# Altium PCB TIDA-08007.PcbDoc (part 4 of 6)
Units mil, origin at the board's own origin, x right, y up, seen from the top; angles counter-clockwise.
Board outline 4212.6 x 2047.24 mil, 10 copper layers (Top Layer, GND 1, Signal Layer 1, GND 2, Split PWR 1, Split PWR 2, GND 3, Signal Layer 2, GND 4, Bottom Layer), stack 66.4 mil thick; 291 components, 178 nets, 1281 pads, 873 vias.
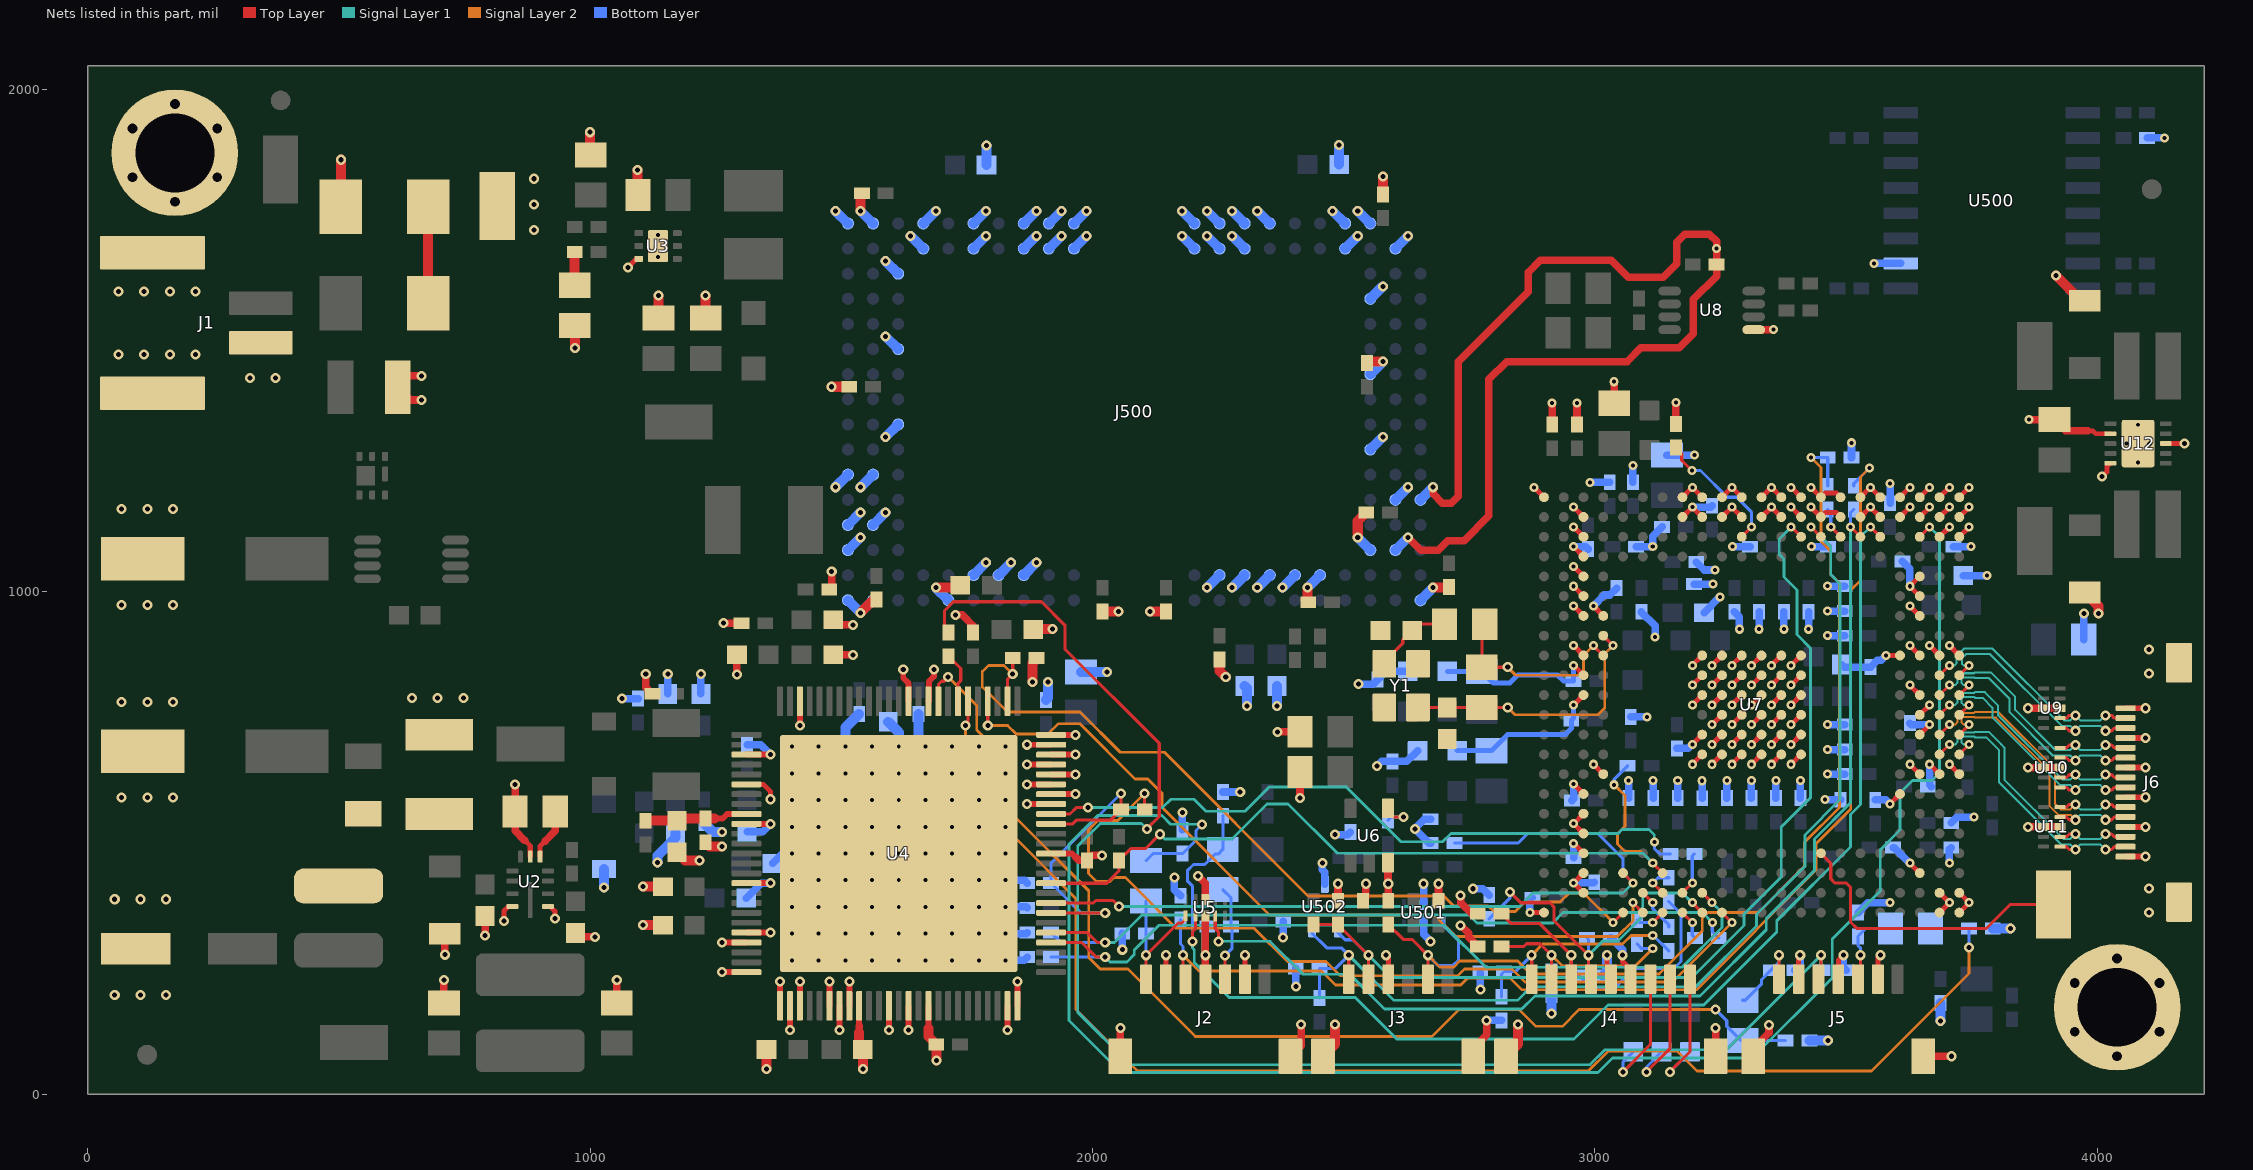
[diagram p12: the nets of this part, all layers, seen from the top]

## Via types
v1: diameter 20, hole 10, Top Layer to Bottom Layer, tented both sides, 439 vias
v2: diameter 18, hole 8, Top Layer to Bottom Layer, tented both sides, 335 vias
v3: diameter 19.68, hole 7.87, Top Layer to Bottom Layer, tented both sides, 72 vias
v4: diameter 19.68, hole 7.87, Top Layer to Bottom Layer, tented bottom, 15 vias
v5: diameter 39.37, hole 19.68, Top Layer to Bottom Layer, 12 vias

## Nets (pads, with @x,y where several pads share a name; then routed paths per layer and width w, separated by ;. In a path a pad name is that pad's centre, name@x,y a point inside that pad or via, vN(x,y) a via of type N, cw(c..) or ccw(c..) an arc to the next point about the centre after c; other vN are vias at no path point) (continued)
GND: C1.2 C2.2 C3.2 C4.2 C6.2 C7.2 C8.1 C9.2 C10.2 C11.2 C13.2 C14.2 C15.2 C16.2 C17.2 C18.2 C19.2 C20.2 C21.2 C22.2 C23.2 C24.2 C25.2 C26.2 C27.2 C28.2 C29.2 C30.2 C31.2 C32.2 C33.2 C34.2 C35.2 C36.2 C37.2 C38.2 C39.2 C40.2 C41.2 C42.2 C43.2 C44.2 C45.2 C46.2 C47.2 C48.2 C49.2 C50.2 C52.2 C53.2 C54.2 C55.2 C500.2 C501.2 C502.2 C503.2 C504.2 C505.2 C506.2 C507.2 C508.2 C509.2 C510.2 C511.2 C512.2 C513.2 C514.2 C515.2 C516.2 C517.2 C518.2 C519.2 C520.2 C521.2 C522.2 C523.2 C524.2 C525.2 C526.2 C527.2 C528.2 C529.2 C530.2 C531.2 C532.2 C533.2 C534.2 C535.2 C536.2 C537.2 C538.2 C539.2 C540.2 C541.2 C542.2 C543.2 C544.2 C545.2 C546.2 C547.2 C548.2 C549.2 C550.2 C551.2 C553.2 C554.2 C556.2 C557.2 C558.2 C559.2 C560.2 C561.2 C564.2 C565.2 C566.2 C567.2 C568.2 C569.2 C570.2 C571.2 C572.2 C573.2 C574.2 C575.2 C576.2 C577.2 C578.2 C579.2 C580.2 C581.2 C582.2 C583.2 C584.2 C585.2 C586.2 C587.2 D1.2 D500.2 FB507.1 FB509.1 J1.2 J1.3 J1.4 J2.2 J2.4 J2.6 J2.8 J2.9 J3.3 J3.7 J3.8 J4.5 J4.6 J4.10 J4.11 J5.2 J5.4 J5.6 J5.8 J5.9 J6.1 J6.4 J6.7 J6.10 J6.13 J6.16 J6.17 J6.18 J500.A3 J500.A4 J500.A7 J500.A8 J500.A9 J500.A10 J500.A11 J500.A12 J500.A13 J500.A15 J500.A17 J500.A19 J500.A20 J500.B2 J500.B4 J500.B8 J500.B9 J500.B10 J500.B11 J500.B12 J500.B13 J500.B15 J500.B17 J500.C18 J500.D3 J500.F18 J500.G3 J500.J18 J500.K3 J500.L19 J500.L20 J500.M1 J500.M2 J500.N19 J500.N20 J500.P2 J500.P3 J500.P20 J500.R5 J500.R6 J500.R7 J500.R8 J500.R9 J500.R13 J500.R14 J500.R15 J500.T1 J500.T16 J500.T19 J500.T20 MH1.1 MH2.1 R3.1 R4.1 R5.1 R7.1 R8.1 R11.1 R12.1 R13.1 R20.1 R21.1 R24.1 R503.1 R505.1 R513.1 R521.1 R527.1 R528.1 R529.1 R530.1 R538.1 R539.1 R541.1 R542.1 R543.1 R544.1 R545.1 R547.1 TP3.1 U2.1 U2.6 U2.11 U3.3 U3.7@1135,1688.5 U4.13 U4.18 U4.19 U4.20 U4.21 U4.22 U4.23 U4.24 U4.25 U4.35 U4.37 U4.48 U4.53 U4.56 U4.60 U4.66 U4.71 U4.72 U4.75 U4.76 U4.77 U4.78 U4.81 U4.82 U4.83 U4.84 U4.87 U4.89 U4.91 U4.99 U4.100 U4.101 U5.3@2224.41,355.21 U5.8@2224.41,388.09 U6.3 U7.A1 U7.A22 U7.AA1 U7.AA2 U7.AA8 U7.AA14 U7.AA20 U7.AA21 U7.AA22 U7.AB1 U7.AB2 U7.AB8 U7.AB14 U7.AB20 U7.AB21 U7.AB22 U7.C2 U7.C3 U7.C4 U7.C5 U7.C6 U7.C7 U7.C14 U7.C16 U7.C17 U7.C18 U7.C19 U7.C20 U7.C21 U7.D8 U7.D16 U7.H21 U7.H22 U7.J9 U7.J10 U7.J12 U7.J13 U7.J14 U7.J21 U7.J22 U7.K9 U7.K10 U7.K11 U7.K12 U7.K13 U7.K14 U7.K21 U7.K22 U7.L9 U7.L10 U7.L11 U7.L12 U7.L13 U7.L14 U7.L21 U7.L22 U7.M9 U7.M10 U7.M11 U7.M12 U7.M13 U7.M14 U7.M21 U7.M22 U7.N9 U7.N10 U7.N11 U7.N12 U7.N13 U7.N14 U7.N21 U7.N22 U7.P9 U7.P10 U7.P11 U7.P12 U7.P13 U7.P14 U7.P21 U7.P22 U7.R21 U7.R22 U7.T21 U7.T22 U7.U21 U7.U22 U7.V21 U7.V22 U7.W7 U7.W14 U7.W21 U7.W22 U7.Y3 U7.Y8 U7.Y10 U7.Y11 U7.Y12 U7.Y14 U7.Y16 U7.Y17 U7.Y18 U7.Y21 U7.Y22 U8.5 U9.3@3925.83,768.49 U9.8@3892.95,768.49 U10.3@3925.83,650.38 U10.8@3892.95,650.38 U11.3@3925.83,532.27 U11.8@3892.95,532.27 U12.2 U12.5 U12.8 U12.11 U500.10 U501.3@2658.95,345.27 U501.8@2658.95,378.14 U502.3 Y1.2 Y1.4 | length 17551.6
  Top Layer w9.45: 3980.55,1320.56 3991.12,1320.56 3996.67,1315.01 U12.2@4025.83,1315.01 ; U12.8@4136.06,1295.32 v1(4172.95,1295.32)
  Top Layer w10: v1(828.18,345.16) 828.18,365.05 836.77,373.64 U2.11@845.26,373.64 ; 869.21,506.07 880.7,494.58 U2.6@880.7,473.05 ; U2.1@916.13,373.64 920.47,373.64 929.52,364.59 v1(929.52,349.82) ; v1(1075,1645.69) 1092.23,1662.91 U3.3@1096.61,1662.91 ; U4.56@1311.02,617.11 1344.73,617.11 1359.28,602.55 v1(1359.28,587.36) ; J2.2@2145.67,229.33 v1(2145.67,276.86) ; J2.6@2303.15,229.33 v1(2303.15,276.86) ; v1(2583.58,276.86) 2588.58,271.86 J3.3@2588.58,229.33 ; v2(2870.58,361.7) U7.A1@2898.42,361.7 ; v2(2878.73,1208.16) U7.A22@2898.42,1188.47 ; v2(2957.47,499.49) U7.C4@2977.16,479.81 ; v2(2957.47,617.61) U7.C7@2977.16,597.92 ; v2(2957.47,893.2) U7.C14@2977.16,873.51 ; v2(2957.47,971.94) U7.C16@2977.16,952.25 ; v2(2957.47,1011.31) U7.C17@2977.16,991.62 ; v2(2957.47,1050.68) U7.C18@2977.16,1030.99 ; v2(2957.47,1090.05) U7.C19@2977.16,1070.36 ; v2(2957.47,1129.42) U7.C20@2977.16,1109.73 ; v2(2957.47,1168.79) U7.C21@2977.16,1149.1 ; U7.C2@2977.16,401.07 v2(2957.47,420.75) U7.C3@2977.16,440.44 ; U7.C5@2977.16,519.18 v2(2957.47,538.86) U7.C6@2977.16,558.55 ; v2(2996.84,656.98) U7.D8@3016.53,637.29 ; v2(2996.84,971.94) U7.D16@3016.53,952.25 ; v1(3024.01,276.86) 3024.01,255.75 3031.5,248.26 J4.5@3031.5,229.33 ; v1(3054.89,276.86) 3054.89,264.37 3070.87,248.4 J4.6@3070.87,229.43 ; U7.H21@3174.01,1149.1 v2(3193.69,1168.79) U7.J21@3213.38,1149.1 ; U7.H22@3174.01,1188.47 v2(3193.69,1208.16) U7.J22@3213.38,1188.47 ; v2(3193.69,656.98) U7.J9@3213.38,676.66 ; v2(3193.69,696.35) U7.J10@3213.38,716.03 ; v2(3193.69,775.09) U7.J12@3213.38,794.77 ; v2(3193.69,814.46) U7.J13@3213.38,834.14 ; v2(3193.69,853.83) U7.J14@3213.38,873.51 ; v2(3233.06,656.98) U7.K9@3252.75,676.66 ; v2(3233.06,696.35) U7.K10@3252.75,716.03 ; v2(3233.06,735.72) U7.K11@3252.75,755.4 ; v2(3233.06,775.09) U7.K12@3252.75,794.77 ; v2(3233.06,814.46) U7.K13@3252.75,834.14 ; v2(3233.06,853.83) U7.K14@3252.75,873.51 ; U7.K21@3252.75,1149.1 v2(3272.43,1168.79) U7.L21@3292.12,1149.1 ; U7.K22@3252.75,1188.47 v2(3272.43,1208.16) U7.L22@3292.12,1188.47 ; v2(3272.43,656.98) U7.L9@3292.12,676.66 ; v2(3272.43,696.35) U7.L10@3292.12,716.03 ; v2(3272.43,735.72) U7.L11@3292.12,755.4 ; v2(3272.43,775.09) U7.L12@3292.12,794.77 ; v2(3272.43,814.46) U7.L13@3292.12,834.14 ; v2(3272.43,853.83) U7.L14@3292.12,873.51 ; v2(3311.8,656.98) U7.M9@3331.49,676.66 ; v2(3311.8,696.35) U7.M10@3331.49,716.03 ; v2(3311.8,735.72) U7.M11@3331.49,755.4 ; v2(3311.8,775.09) U7.M12@3331.49,794.77 ; v2(3311.8,814.46) U7.M13@3331.49,834.14 ; v2(3311.8,853.83) U7.M14@3331.49,873.51 ; U7.M21@3331.49,1149.1 v2(3351.17,1168.79) U7.N21@3370.86,1149.1 ; U7.M22@3331.49,1188.47 v2(3351.17,1208.16) U7.N22@3370.86,1188.47 ; v2(3351.17,656.98) U7.N9@3370.86,676.66 ; v2(3351.17,696.35) U7.N10@3370.86,716.03 ; v2(3351.17,735.72) U7.N11@3370.86,755.4 ; v2(3351.17,775.09) U7.N12@3370.86,794.77 ; v2(3351.17,814.46) U7.N13@3370.86,834.14 ; v2(3351.17,853.83) U7.N14@3370.86,873.51 ; v2(3390.54,656.98) U7.P9@3410.23,676.66 ; v2(3390.54,696.35) U7.P10@3410.23,716.03 ; v2(3390.54,735.72) U7.P11@3410.23,755.4 ; v2(3390.54,775.09) U7.P12@3410.23,794.77 ; v2(3390.54,814.46) U7.P13@3410.23,834.14 ; v2(3390.54,853.83) U7.P14@3410.23,873.51 ; v2(3390.54,1168.79) U7.P21@3410.23,1149.1 ; v2(3390.54,1208.16) U7.P22@3410.23,1188.47 ; J5.2@3405.51,229.33 3405.51,273.86 v1(3408.51,276.86) ; v2(3429.91,1168.79) U7.R21@3449.6,1149.1 3458.52,1158.03 3480.04,1158.03 U7.T21@3488.97,1149.1 ; v2(3429.91,1208.16) U7.R22@3449.6,1188.47 3458.3,1197.18 3480.26,1197.18 U7.T22@3488.97,1188.47 ; J5.4@3484.25,229.33 3484.25,266.86 v1(3494.25,276.86) ; U7.U21@3528.34,1149.1 v2(3548.02,1168.79) U7.V21@3567.71,1149.1 ; U7.U22@3528.34,1188.47 v2(3548.02,1208.16) U7.V22@3567.71,1188.47 ; J5.6@3562.99,229.33 3562.99,271.86 v1(3567.99,276.86) ; v2(3579.24,873.51) U7.W14@3607.08,873.51 ; v2(3587.39,578.24) U7.W7@3607.08,597.92 ; U7.W21@3607.08,1149.1 v2(3626.76,1168.79) ; U7.W22@3607.08,1188.47 v2(3626.76,1208.16) ; v2(3626.76,460.12) U7.Y3@3646.45,440.44 ; v2(3626.76,656.98) U7.Y8@3646.45,637.29 ; v2(3626.76,814.46) U7.Y12@3646.45,794.77 ; v2(3626.76,893.2) U7.Y14@3646.45,873.51 ; v2(3626.76,971.94) U7.Y16@3646.45,952.25 ; U7.Y10@3646.45,716.03 v2(3666.13,735.72) ; U7.Y11@3646.45,755.4 v2(3666.13,775.09) ; U7.Y17@3646.45,991.62 v2(3626.76,1011.31) U7.Y18@3646.45,1030.99 ; U7.Y21@3646.45,1149.1 v2(3666.13,1168.79) ; U7.Y22@3646.45,1188.47 v2(3666.13,1208.16) ; v2(3666.13,656.98) U7.AA8@3685.82,637.29 ; v2(3666.13,893.2) U7.AA14@3685.82,873.51 ; U7.AA1@3685.82,361.7 v2(3705.5,381.38) U7.AA2@3685.82,401.07 ; U7.AA20@3685.82,1109.73 v2(3705.5,1129.42) ; U7.AA21@3685.82,1149.1 v2(3705.5,1168.79) ; U7.AA22@3685.82,1188.47 v2(3705.5,1208.16) ; v2(3705.5,656.98) U7.AB8@3725.19,637.29 ; v2(3705.5,893.2) U7.AB14@3725.19,873.51 ; U7.AB1@3725.19,361.7 v2(3744.87,381.38) U7.AB2@3725.19,401.07 ; U7.AB20@3725.19,1109.73 v2(3744.87,1129.42) ; U7.AB21@3725.19,1149.1 v2(3744.87,1168.79) ; U7.AB22@3725.19,1188.47 v2(3744.87,1208.16) ; v1(4009.48,1229.77) 4018.89,1239.18 4018.89,1249.02 U12.5@4025.83,1255.95
  Top Layer w11.81: v1(1262.73,243.09) U4.75@1311.02,243.09 ; v1(1262.73,302.14) U4.72@1311.02,302.14 ; U4.71@1311.02,321.83 v1(1359.32,321.83) ; U4.66@1311.02,420.25 v1(1359.32,420.25) ; U4.60@1311.02,538.36 v1(1359.32,538.36) ; U4.53@1311.02,676.16 v1(1359.32,676.16) ; U4.76@1377.95,176.16 v1(1377.95,224.46) ; v1(1397.64,127.86) U4.77@1397.64,176.16 ; U4.78@1417.32,176.16 v1(1417.32,224.46) ; v1(1417.32,734.16) U4.48@1417.32,782.46 ; U4.81@1476.38,176.16 v1(1476.38,224.46) ; v1(1496.06,127.86) U4.82@1496.06,176.16 ; U4.83@1515.75,176.16 v1(1515.75,224.46) ; 1535.43,136.34 U4.84@1535.43,176.16 ; v1(1594.49,127.86) U4.87@1594.49,176.16 ; v1(1623.11,845.28) 1623.11,828.74 1633.86,817.99 U4.37@1633.86,782.46 ; v1(1633.86,127.86) U4.89@1633.86,176.16 ; 1673.23,131.01 U4.91@1673.23,176.16 ; U4.35@1673.23,782.46 1673.95,783.18 1673.95,821.6 1683.98,831.63 v1(1683.98,845.28) ; v1(1830.71,127.86) U4.99@1830.71,176.16 ; U4.100@1850.39,176.16 v1(1850.39,224.46) ; v1(1869.02,577.74) U4.18@1917.32,577.74 ; v1(1869.02,617.11) U4.20@1917.32,617.11 ; v1(1869.02,656.48) U4.22@1917.32,656.48 ; v1(1869.02,695.85) U4.24@1917.32,695.85 ; U4.13@1917.32,479.31 1958.66,479.31 1966.26,471.71 ; U4.19@1917.32,597.42 v1(1965.62,597.42) ; U4.21@1917.32,636.79 v1(1965.62,636.79) ; U4.23@1917.32,676.16 v1(1965.62,676.16) ; U4.25@1917.32,715.53 v1(1965.62,715.53) ; J6.1@4056.1,473.22 v1(4095.79,473.22) ; J6.4@4056.1,532.27 v1(4095.79,532.27) ; J6.7@4056.1,591.33 v1(4095.79,591.33) ; J6.10@4056.1,650.38 v1(4095.79,650.38) ; J6.13@4056.1,709.44 v1(4095.79,709.44) ; J6.16@4056.1,768.49 v1(4095.79,768.49)
  Top Layer w15: v1(664.11,1382.05) 642.56,1382.05 C4.2@617.13,1407.48 639.54,1429.9 v1(664.11,1429.9) ; C7.2@708.88,182.14 v1(708.88,227.21) ; v1(710.7,277.85) C8.1@710.7,319.51 ; v1(790.7,316.33) C9.2@790.7,354.94 ; v1(850.54,616.44) C10.2@850.54,562.93 850.54,524.74 869.21,506.07 ; C13.2@970.7,321.28 978.65,313.32 v1(1009.3,313.32) ; C14.2@1052.9,182.14 v1(1052.9,227.21) ; v1(1110.59,836.93) 1110.59,810.67 C17.2@1124.02,797.24 ; v1(1265.43,937.78) R4.1@1301.18,937.78 ; v1(1291.96,835.23) C23.2@1291.96,874.92 ; R5.1@1475.76,1005.07 1480.76,1010.07 v1(1480.76,1040.82) ; C26.2@1483.63,874.85 v1(1523.32,874.85) ; C25.2@1483.63,944.48 1493.63,934.48 v1(1523.32,934.48) ; 1535.43,122.59 1535.43,136.34 ; v1(1727.08,954.12) 1740.15,954.12 1762.08,932.19 R7.1@1762.08,919.27 ; 1966.26,471.71 1972.44,465.53 C34.2@1988.91,465.53 1998.91,475.53 v1(2018.72,475.53) ; J2.8@2055.12,75.79 v1(2055.12,132.09) ; v1(2209.64,435) 2224.41,420.22 U5.8@2224.41,388.09 ; J2.4@2224.41,229.33 v1(2224.41,276.86) U5.3@2224.41,355.21 ; v1(2367.83,721.47) R13.1@2412.83,721.47 ; J2.9@2393.7,75.79 2414.93,97.01 v1(2414.93,138.86) ; v1(2412.83,589.97) R12.1@2412.83,641.47 ; C38.2@2488.48,385.39 v1(2488.48,419.14) ; C39.2@2538.48,385.39 2543.98,390.89 v1(2543.98,419.14) ; U6.3@2587.97,460.98 2587.97,419.65 v1(2588.48,419.14) C44.2@2588.48,385.39 ; v1(2627.76,1108.39) 2652.97,1083.17 2687.67,1083.17 2706.69,1102.19 2739.74,1102.19 2788.99,1151.43 2788.99,1423.41 2824.07,1458.5 3063.69,1458.5 3091.19,1486 3167.59,1486 3195.76,1514.17 3195.76,1582.38 3241.94,1628.56 C52.2@3241.94,1651.82 v2(3241.94,1683.17) 3241.94,1697.65 3227.8,1711.79 3178.67,1711.79 3162.62,1695.74 3162.62,1653.11 3136.11,1626.6 3066.06,1626.6 3032.3,1660.36 2891.49,1660.36 2866.94,1635.81 2866.94,1597.59 2727.63,1458.28 2727.63,1190.21 2713.94,1176.51 2696.3,1176.51 2677.76,1195.05 v1(2677.76,1208.39) ; C45.2@2688.48,385.39 v1(2688.48,419.14) ; v1(2732.61,336.05) 2748.42,320.24 2748.42,312.64 R20.1@2766.73,294.33 ; v1(2732.61,396.05) 2732.61,381.54 2754.82,359.33 R21.1@2766.73,359.33 ; J3.8@2757.87,75.79 2757.87,92.66 2784.17,118.95 v1(2784.17,147.09) ; C48.2@2914.84,1333.09 v2(2914.84,1376.01) ; C49.2@2964.21,1333.09 v2(2964.21,1376.01) ; C50.2@3038.27,1375.47 v2(3038.27,1418.38) ; R24.1@3160.88,1334.46 v2(3160.88,1377.38) ; J4.11@3240.16,75.79 v1(3240.16,132.09) ; J5.8@3314.96,75.79 3314.96,91.1 3346.36,122.51 v1(3346.36,138) ; U8.5@3315.89,1522 v2(3355.53,1522) ; J5.9@3653.54,75.79 v1(3709.84,75.79) ; v1(3861.83,532.27) U11.8@3892.95,532.27 U11.3@3925.83,532.27 ; v1(3861.83,650.38) U10.8@3892.95,650.38 U10.3@3925.83,650.38 ; v1(3861.83,768.49) U9.8@3892.95,768.49 U9.3@3925.83,768.49 ; v2(3864.05,1342.84) C53.2@3914.55,1342.84 3936.83,1320.56 3980.55,1320.56
  Top Layer w20: D1.2@503.54,1766.81 v1(503.54,1860.22) ; v1(969.94,1485.36) C11.2@969.94,1530.19 ; R3.1@1000.06,1870.17 v1(1000.06,1915) ; C15.2@1094.25,1790.17 v1(1094.25,1840) ; v1(1105.18,336.63) C18.2@1144.86,336.63 ; v1(1105.18,413.39) C19.2@1144.86,413.39 ; C16.2@1135.84,1544.88 v1(1135.84,1589.71) ; C20.2@1172.64,481.73 1188.69,465.68 v1(1217.71,465.68) ; C21.2@1229.41,1545.06 v1(1229.41,1589.88) ; C22.2@1229.68,501.59 1237.93,493.34 v1(1262.03,493.34) ; v1(1351.02,50.46) C24.2@1351.02,89.16 ; v1(1479.89,1408.39) C28.2@1515.75,1408.39 ; 1535.43,122.59 1535.43,96.41 C27.2@1542.68,89.16 v1(1542.68,50.46) ; v1(1537.99,958.39) 1564.37,984.76 C30.2@1569.8,984.76 ; v1(1537.99,1758.39) 1537.99,1790.83 C29.2@1540.75,1793.59 ; 1673.23,131.01 1673.23,115.03 C31.2@1688.98,99.29 v1(1688.98,67.47) ; v1(1687.99,1008.39) 1731.62,1008.39 C32.2@1736.62,1013.39 ; v1(1880.27,820.44) 1880.27,858.15 R8.1@1890.27,868.15 ; C33.2@1881.83,926.44 v1(1920.21,926.44) ; C35.2@2019.85,961.14 v1(2051.7,961.14) ; v1(2114.05,961.14) C36.2@2145.9,961.14 ; R11.1@2252.76,865.43 2252.76,842.69 v1(2265.01,830.43) ; v1(2427.76,1008.39) 2427.76,980.9 C37.2@2429.13,979.52 ; J3.7@2458.66,75.79 2482.89,100.01 v1(2482.89,138.86) ; v1(2527.76,1108.39) 2527.76,1141.38 C40.2@2544.76,1158.39 ; C41.2@2545.94,1455.63 2548.7,1458.39 v1(2577.76,1458.39) ; C43.2@2577.76,1791.38 v1(2577.76,1827.23) ; v1(2677.76,1008.39) 2708.19,1008.39 C47.2@2709.57,1009.76 ; J4.10@2822.83,75.79 2847.06,100.01 v1(2847.06,138.86) ; v1(3917.43,1629.82) 3967.48,1579.77 C54.2@3974.55,1579.77 ; C55.2@3974.55,999.06 4001.78,971.83 v1(4001.78,956.82)
  Bottom Layer w15: v1(1063.69,787.63) R547.1@1095.5,787.63 ; C587.2@1154.41,796.97 v1(1154.41,836.93) ; C585.2@1220.37,796.97 v1(1220.37,836.93) ; C583.2@1310.53,390.52 1340.27,420.25 v1(1359.32,420.25) ; C582.2@1312.24,522.75 1343.71,522.75 v1(1359.32,538.36) ; C584.2@1312.24,696 1339.49,696 v1(1359.32,676.16) ; C581.2@1363.02,459.62 1382.7,479.31 v3(1401.57,479.31) ; v3(1826.77,266.71) 1864.33,266.71 R541.1@1870.08,272.46 ; v3(1826.77,319.86) 1868.11,319.86 R544.1@1870.08,321.83 ; v3(1826.77,373.01) 1868.27,373.01 R543.1@1870.08,371.2 ; v3(1826.77,426.16) 1864.49,426.16 R542.1@1870.08,420.57 ; v1(2059.06,287.81) C574.2@2059.06,320.27 ; v1(2162.97,431.87) 2162.97,407.6 C573.2@2175.18,395.39 ; R539.1@2178.91,526.3 v1(2178.91,560.91) ; v1(2224.41,276.86) 2224.41,330.57 C572.2@2228.11,334.27 ; R538.1@2259.26,601.75 v1(2293.87,601.75) ; v1(2379.41,311.81) C569.2@2379.41,344.27 ; v1(2404.47,214.86) C568.2@2404.47,250.67 ; v1(2457.4,460.88) 2457.4,447.02 2462.4,442.02 U502.3@2462.4,417.89 ; v1(2482.41,517.01) 2508.16,517.01 C566.2@2513.16,522.01 ; v1(2529.59,816.61) 2558.4,816.61 C565.2@2567.4,825.61 2583.78,841.98 FB509.1@2627.37,841.98 ; v1(2566.26,653.61) 2575.26,662.61 C564.2@2597.02,662.61 2625.6,662.61 FB507.1@2646.98,683.98 ; U501.3@2658.95,345.27 2658.95,318.37 v1(2672.78,304.54) ; U501.8@2658.95,378.14 v1(2658.95,419.14) ; R530.1@2672.81,500.19 2669.8,500.19 v1(2641.51,528.48) 2660.46,547.42 R529.1@2672.81,547.42 ; v1(2757.31,409.18) 2776.92,409.18 R528.1@2789.45,396.66 ; v1(2771.73,208.52) C560.2@2771.73,244.33 ; v1(2784.17,147.09) R527.1@2813.98,147.09 ; v2(2870.58,361.7) 2870.58,386.48 C559.2@2875.48,391.38 ; C554.2@2954.26,584.86 2957.47,588.07 v2(2957.47,617.61) ; v2(2957.47,420.75) 2997.34,420.75 C556.2@2998.59,422.01 ; C553.2@2957.47,470.68 v2(2957.47,499.49) ; v2(2957.47,1090.05) 2981.77,1090.05 C558.2@2986.34,1085.47 ; v2(2989.6,1218.26) C551.2@3029.29,1218.26 ; v2(2996.84,971.94) 3018.81,993.91 3029.27,993.91 C549.2@3043.1,1007.74 ; C550.2@3031.5,311.2 3054.89,287.81 v1(3054.89,276.86) ; C548.2@3067.02,589.64 v2(3067.02,624.39) ; C547.2@3071.12,751.2 v2(3103.81,751.2) ; C546.2@3075.58,1218.26 v2(3075.58,1251.95) ; C545.2@3081.77,1090.05 v2(3114.95,1090.05) 3114.95,1110.92 C539.2@3133.45,1129.42 ; C544.2@3092.31,960.5 3092.31,959.63 3119.53,932.42 v2(3119.53,910.14) ; C543.2@3115.88,589.64 v2(3115.88,624.39) ; C542.2@3143.19,1272.47 v2(3198.16,1272.47) ; C541.2@3162.88,688.47 3185.82,688.47 v2(3193.69,696.35) ; C540.2@3164.73,589.64 v2(3164.73,624.39) ; v2(3193.69,1168.79) 3230.41,1168.79 C534.2@3233.06,1171.44 ; C538.2@3197.19,1015.68 v2(3234.95,1015.68) ; C537.2@3201.56,1059.24 3217.14,1043.66 v2(3238.65,1043.66) ; C536.2@3213.38,589.43 v2(3213.38,624.18) ; C535.2@3217.05,958.54 v2(3248.52,990.01) ; C533.2@3262.44,589.64 v2(3262.44,624.39) ; v2(3273.8,1090.05) C529.2@3308.55,1090.05 ; C532.2@3277.43,960.5 3287.43,950.5 v2(3287.43,925.75) ; C531.2@3311.29,589.64 v2(3311.29,624.39) ; v2(3326.64,925.75) C530.2@3326.64,960.5 ; C528.2@3360.14,589.64 v2(3360.14,624.39) ; v2(3375.86,925.75) C527.2@3375.86,960.5 ; C526.2@3397.32,247.05 3408.51,258.24 v1(3408.51,276.86) ; C525.2@3408.99,589.64 v2(3408.99,624.39) ; v2(3425.07,925.75) C524.2@3425.07,960.5 ; v2(3431.28,1090.05) C520.2@3464.03,1090.05 ; v2(3458.16,586.49) C523.2@3488.97,586.49 ; v2(3462.44,637.29) C514.2@3497.25,637.29 ; v2(3462.44,686.25) C513.2@3497.25,686.25 ; v2(3462.44,736.03) C512.2@3497.25,736.03 ; v2(3462.44,912.88) C517.2@3497.25,912.88 ; v2(3462.44,961.84) C516.2@3497.25,961.84 ; v2(3462.44,1011.62) C515.2@3497.25,1011.62 ; C522.2@3490.92,855.3 3495.7,850.51 C518.2@3548.37,850.51 3561.72,863.86 3569.59,863.86 v2(3579.24,873.51) ; v1(3494.25,276.86) 3494.25,253.11 C521.2@3500.32,247.05 ; R513.1@3510.54,1267.25 v2(3510.54,1296.91) ; C519.2@3523.62,361.7 3543.3,381.38 v2(3587.39,381.38) ; v2(3555.43,1653.81) U500.10@3608.88,1653.81 ; C511.2@3557.96,586.49 3579.14,586.49 v2(3587.39,578.24) ; C510.2@3587.39,1176.66 v2(3587.39,1216.03) ; C509.2@3593.26,491.01 3595.88,491.01 v2(3626.76,460.12) ; C508.2@3612.01,1060.7 3626.76,1045.95 v2(3626.76,1011.31) ; C507.2@3626.76,738.9 3629.95,735.72 v2(3666.13,735.72) ; v2(3666.13,656.98) 3666.13,615.95 C506.2@3669.42,612.66 ; v2(3705.5,460.12) 3705.5,487.49 C504.2@3709.01,490.99 ; C503.2@3709.01,540.36 3720.35,551.7 v2(3754.34,551.7) ; C502.2@3713.38,1090.05 v2(3748.19,1090.05) ; C501.2@3733.06,1032.5 v2(3780.45,1032.5) ; R503.1@3972.95,905.32 v1(3972.95,956.82) ; C500.2@4099.04,1903.81 v2(4133.78,1903.81)
  Bottom Layer w20: v1(1027.75,411.36) D500.2@1027.75,448.76 ; v1(1133.94,461.65) 1133.94,475.04 1170.02,511.12 R545.1@1170.02,519.86 ; C586.2@1227.06,539.71 1244.88,521.89 v1(1262.03,521.89) ; v1(1487.99,1208.39) J500.L20@1512.99,1233.39 ; v1(1487.99,1758.39) J500.A20@1512.99,1733.39 ; v3(1507.87,691.91) 1507.87,729.73 C580.2@1535.43,757.29 ; J500.T20@1512.99,983.39 v1(1537.99,958.39) J500.T19@1562.99,983.39 ; J500.P20@1512.99,1083.39 v1(1537.99,1108.39) ; J500.N20@1512.99,1133.39 v1(1537.99,1158.39) ; v1(1537.99,1208.39) J500.L19@1562.99,1233.39 ; v1(1537.99,1758.39) J500.A19@1562.99,1733.39 ; J500.N19@1562.99,1133.39 v1(1587.99,1158.39) ; v1(1587.99,1308.39) J500.J18@1612.99,1333.39 ; v1(1587.99,1508.39) J500.F18@1612.99,1483.39 ; v1(1587.99,1658.39) J500.C18@1612.99,1633.39 ; C579.2@1593.2,741.54 1614.17,720.57 v3(1614.17,691.91) ; v1(1637.99,1708.39) J500.B17@1662.99,1683.39 ; C578.2@1653.54,757.29 1653.54,705.69 v3(1667.32,691.91) ; J500.A17@1662.99,1733.39 v1(1687.99,1758.39) ; v1(1687.99,1008.39) J500.T16@1712.99,983.39 ; J500.R15@1762.99,1033.39 v1(1787.99,1058.39) ; J500.B15@1762.99,1683.39 v1(1787.99,1708.39) ; J500.A15@1762.99,1733.39 v1(1787.99,1758.39) ; C577.2@1788.91,1849.63 v1(1788.91,1888.33) ; J500.R14@1812.99,1033.39 v1(1837.99,1058.39) ; J500.R13@1862.99,1033.39 v1(1887.99,1058.39) ; J500.B13@1862.99,1683.39 v1(1887.99,1708.39) ; J500.A13@1862.99,1733.39 v1(1887.99,1758.39) ; C576.2@1906.98,784.7 1910.98,788.7 v1(1910.98,820.44) ; J500.B12@1912.99,1683.39 v1(1937.99,1708.39) ; J500.A12@1912.99,1733.39 v1(1937.99,1758.39) ; J500.B11@1962.99,1683.39 v1(1987.99,1708.39) ; J500.A11@1962.99,1733.39 v1(1987.99,1758.39) ; C575.2@1977.07,840.53 v1(2028.57,840.53) ; v1(2177.76,1708.39) J500.B10@2202.76,1683.39 ; v1(2177.76,1758.39) J500.A10@2202.76,1733.39 ; v1(2227.76,1008.39) J500.R9@2252.76,1033.39 ; v1(2227.76,1708.39) J500.B9@2252.76,1683.39 ; v1(2227.76,1758.39) J500.A9@2252.76,1733.39 ; v1(2277.76,1008.39) J500.R8@2302.76,1033.39 ; v1(2277.76,1708.39) J500.B8@2302.76,1683.39 ; v1(2277.76,1758.39) J500.A8@2302.76,1733.39 ; C571.2@2302.76,812.99 2307.36,808.39 v1(2307.36,773.25) ; v1(2327.76,1008.39) J500.R7@2352.76,1033.39 ; v1(2327.76,1758.39) J500.A7@2352.76,1733.39 ; v1(2366.91,773.31) C570.2@2366.91,812.99 ; v1(2377.76,1008.39) J500.R6@2402.76,1033.39 ; v1(2427.76,1008.39) J500.R5@2452.76,1033.39 ; v1(2477.76,1758.39) J500.A4@2502.76,1733.39 ; C567.2@2490.75,1850.8 v1(2490.75,1889.51) ; J500.B4@2502.76,1683.39 v1(2527.76,1708.39) ; v1(2527.76,1108.39) J500.P3@2552.76,1083.39 ; v1(2527.76,1758.39) J500.A3@2552.76,1733.39 ; J500.K3@2552.76,1283.39 v1(2577.76,1308.39) ; J500.G3@2552.76,1433.39 v1(2577.76,1458.39) ; J500.D3@2552.76,1583.39 v1(2577.76,1608.39) ; J500.P2@2602.76,1083.39 v1(2627.76,1108.39) ; J500.M2@2602.76,1183.39 v1(2627.76,1208.39) ; J500.B2@2602.76,1683.39 v1(2627.76,1708.39) ; J500.T1@2652.76,983.39 v1(2677.76,1008.39) ; J500.M1@2652.76,1183.39 v1(2677.76,1208.39) ; v1(2913.39,161.11) C557.2@2913.39,197.8 ; C561.2@3015.86,236.3 3024.01,244.45 v1(3024.01,276.86) ; R521.1@3426.71,107.36 v1(3463.4,107.36) ; v1(3687.54,146.34) C505.2@3687.54,182.09 ; R505.1@3791.63,330.08 v1(3827.38,330.08)
  other v1: 53.61,197.58 104.61,197.58 155.62,197.58 4102.32,361.6 53.61,388.28 104.61,388.28 155.62,388.28 4102.32,409.45 67.39,590.47 118.39,590.47 169.4,590.47 67.39,781.17 118.39,781.17 169.4,781.17 645.39,788.69 696.4,788.69 747.41,788.69 4102.32,837.98 4102.32,885.83 67.39,974.33 118.39,974.33 169.4,974.33 67.39,1165.03 118.39,1165.03 169.4,1165.03 322.48,1425.71 373.48,1425.71 61.25,1472.81 112.26,1472.81 163.26,1472.81 214.27,1472.81 61.25,1598.05 112.26,1598.05 163.26,1598.05 214.27,1598.05 888.16,1720.4 888.16,1771.41 888.16,1822.41
  other v3: 1401.57,266.71 1454.72,266.71 1507.87,266.71 1561.02,266.71 1614.17,266.71 1667.32,266.71 1720.47,266.71 1773.62,266.71 1401.57,319.86 1454.72,319.86 1507.87,319.86 1561.02,319.86 1614.17,319.86 1667.32,319.86 1720.47,319.86 1773.62,319.86 1401.57,373.01 1454.72,373.01 1507.87,373.01 1561.02,373.01 1614.17,373.01 1667.32,373.01 1720.47,373.01 1773.62,373.01 1401.57,426.16 1454.72,426.16 1507.87,426.16 1720.47,426.16 1773.62,426.16 1454.72,479.31 1507.87,479.31 1720.47,479.31 1773.62,479.31 1826.77,479.31 1401.57,532.46 1454.72,532.46 1507.87,532.46 1720.47,532.46 1773.62,532.46 1826.77,532.46 1401.57,585.61 1454.72,585.61 1507.87,585.61 1561.02,585.61 1614.17,585.61 1667.32,585.61 1720.47,585.61 1773.62,585.61 1826.77,585.61 1401.57,638.76 1454.72,638.76 1507.87,638.76 1561.02,638.76 1614.17,638.76 1667.32,638.76 1720.47,638.76 1773.62,638.76 1826.77,638.76 1401.57,691.91 1454.72,691.91 1561.02,691.91 1720.47,691.91 1773.62,691.91 1826.77,691.91
  other v4: 1561.02,426.16 1614.17,426.16 1667.32,426.16 1561.02,479.31 1614.17,479.31 1667.32,479.31 1561.02,532.46 1614.17,532.46 1667.32,532.46 4080.94,1257.92 4058.31,1295.32 4103.58,1295.32 4080.94,1332.72 1135,1666.85 1135,1710.16
  other v5: 4039.37,75.79 3954.98,124.51 4123.76,124.51 3954.98,221.95 4123.76,221.95 4039.37,270.67 173.23,1776.57 88.84,1825.3 257.61,1825.3 88.84,1922.74 257.61,1922.74 173.23,1971.46
GND11AD_PLLD: C555.2 C562.2 FB507.2 U7.C12 | length 322.2
  Top Layer w10: v2(2957.47,775.09) U7.C12@2977.16,794.77
  Bottom Layer w10: FB507.2@2725.72,683.98 C562.2@2794.05,683.98 2826.09,716.03 2940.84,716.03 2952.85,728.04 C555.2@2952.85,744.27 2957.47,748.9 v2(2957.47,775.09)
GND11AD_PLLM: C552.2 C563.2 FB509.2 U7.C13 | length 330.9
  Top Layer w10: v2(2957.47,853.83) U7.C13@2977.16,834.14
  Bottom Layer w10: FB509.2@2706.11,841.98 C563.2@2774.43,841.98 2797.69,818.72 2830.55,818.72 2846.3,834.47 2925.45,834.47 2936.91,823.01 C552.2@2957.47,823.01 v2(2957.47,853.83)
HB_B: R532.2 U6.4 | length 76.7
  Top Layer w6.2: U6.4@2587.97,569.25 2587.97,561.87 2597.58,552.25 v1(2619.17,552.25)
  Bottom Layer w6.2: R532.2@2587.97,545.25 2594.97,552.25 v1(2619.17,552.25)
HOST_I2C_SCL: C568.1 J3.1 R534.1 U7.R20 U502.2 | length 2100.3
  Top Layer w6.2: J3.1@2509.84,229.33 v1(2509.84,276.86) ; v2(3429.91,1129.42) U7.R20@3449.6,1109.73
  Signal Layer 1 w5.6: v1(2509.84,276.86) 2599.61,187.09 2845.6,187.09 2872.74,214.23 3200.57,214.23 3321.59,335.25 3321.59,357.73 3417.81,453.95 3417.81,516.45 3487.97,586.61 3487.97,1015.76 3469.19,1034.53 3469.19,1090.14 v2(3429.91,1129.42)
  Bottom Layer w6.2: U502.2@2436.81,329.31 2436.81,320.92 2466.14,291.6 2495.1,291.6 v1(2509.84,276.86) 2483.65,250.67 C568.1@2451.71,250.67 R534.1@2451.71,191.81
HOST_I2C_SDA: C38.1 J3.2 R15.1 U7.P20 U502.1 | length 1990.3
  Top Layer w6.2: R15.1@2439.51,338.14 C38.1@2488.48,338.14 2488.48,337.59 v1(2549.21,276.86) J3.2@2549.21,229.33 ; v2(3390.54,1129.42) U7.P20@3410.23,1109.73
  Signal Layer 1 w5.6: v1(2549.21,276.86) 2593.58,232.49 3193.09,232.49 3296.65,336.04 3296.65,358.42 3370.86,432.63 3370.86,531.9 3429.17,590.21 3429.17,887.84 3401.89,915.12 3401.89,1003.75 3376.13,1029.52 3376.13,1065.53 3366.73,1074.93 3366.73,1105.61 v2(3390.54,1129.42)
  Bottom Layer w6.2: U502.1@2487.99,329.31 2487.99,322.66 2502.85,307.8 2518.27,307.8 v1(2549.21,276.86)
HOST_IF_SEL: TP10.1 U7.R4 | length 603.9
  Top Layer w6.2: U7.R4@3449.6,479.81 3469.28,460.12 3469.28,428.84 3477.36,420.75 3500.35,420.75 3508.65,412.46 3508.65,342.87 3521.73,329.79 3778.32,329.79 3826.15,377.61 TP10.1@3912.44,377.61
HOST_IRQ: C44.1 J3.5 R513.2 R516.1 U501.1 | length 2149.5
  Top Layer w6.2: C44.1@2588.48,338.14 2618.26,308.36 2635.82,308.36 v1(2667.32,276.86) J3.5@2667.32,229.33
  Signal Layer 2 w5.6: v1(2667.32,276.86) 2690.48,253.7 2719.05,253.7 2730.58,265.24 2846.33,265.24 2872.11,239.45 3127.73,239.45 3213.43,325.15 3213.43,350.65 3224.83,362.06 3325.21,362.06 3416.57,453.42 3416.57,501.4 3486.41,571.25 3486.41,1017.6 3469.33,1034.68 3469.33,1080.95 3449.62,1100.66 3449.62,1247.66 v2(3430.03,1267.25)
  Bottom Layer w6.2: v1(2667.32,276.86) 2688.26,255.92 2716.91,255.92 2728.23,267.24 2728.23,305.36 2698.32,335.27 U501.1@2698.32,345.27 ; v2(3430.03,1267.25) R513.2@3463.3,1267.25 R516.1@3463.3,1211.41
HOST_IRQ_S: R516.2 U7.T20 | length 65.1
  Top Layer w6.2: v2(3469.28,1129.42) U7.T20@3488.97,1109.73
  Bottom Layer w6.2: R516.2@3463.3,1164.16 3469.28,1158.18 v2(3469.28,1129.42)
HOST_SPI_CLK: R539.2 R540.2 U7.Y20 | length 3485
  Top Layer w6.2: U7.Y20@3646.45,1109.73 v2(3666.13,1129.42)
  Signal Layer 1 w5.6: v1(2218.09,537.53) 2155.27,537.53 2137.83,554.97 2009.52,554.97 1953.04,498.49 1953.04,147.04 2056.61,43.46 3005.72,43.46 3034.59,72.33 3312.74,72.33 3472.12,231.71 3472.12,309.4 3567.69,404.97 3567.69,486.3 3607.3,525.91 3607.3,599.87 3632.03,624.59 3670.54,624.59 3685.84,639.89 3685.84,1109.71 v2(3666.13,1129.42)
  Bottom Layer w6.2: R540.2@2106.3,465.06 2120.3,479.06 R539.2@2178.91,479.06 2205.79,505.94 2205.79,525.22 v1(2218.09,537.53)
HOST_SPI_CLK_S: C574.1 J2.1 R540.1 U5.1 | length 270.9
  Top Layer w6.2: J2.1@2106.3,229.33 v1(2106.3,276.86) 2170.59,341.15 2177.8,341.15 2185.04,348.39 U5.1@2185.04,355.21
  Bottom Layer w6.2: v1(2106.3,276.86) C574.1@2106.3,320.27 R540.1@2106.3,385.06
HOST_SPI_MISO: C573.1 J2.3 R512.1 | length 2414.1
  Top Layer w6.2: v1(2180.04,276.86) 2180.04,234.43 J2.3@2185.04,229.43
  Signal Layer 2 w5.6: v1(2180.04,276.86) 2211.58,245.32 2455.77,245.32 2483.52,217.57 2732.68,217.57 2746.82,231.7 2830.69,231.7 2854.39,208.01 3201.74,208.01 3440.1,446.36 3440.1,498.75 3509.02,567.67 3509.02,1003.86 3528.26,1023.1 3528.26,1228.46 v2(3546.33,1246.54)
  Bottom Layer w6.2: C573.1@2175.18,348.14 2175.18,299.14 2180.04,294.28 v1(2180.04,276.86) ; R512.1@3515.01,1211.41 3515.01,1215.22 v2(3546.33,1246.54)
HOST_SPI_MISO_S: R512.2 U5.4 U7.U20 | length 2201.7
  Top Layer w6.2: U5.4@2244.09,355.21 2244.09,329.8 2250.27,323.62 v1(2250.27,304.53) ; v2(3508.65,1129.42) U7.U20@3528.34,1109.73
  Signal Layer 1 w5.6: v1(2250.27,304.53) 2352.97,304.53 2418.48,239.02 2511.76,239.02 2581.21,169.56 2854.28,169.56 2880.29,195.57 3208.79,195.57 3340.93,327.71 3340.93,350.18 3436.66,445.92 3436.66,508.35 3508.65,580.33 v2(3508.65,1129.42)
  Bottom Layer w6.2: v2(3508.65,1129.42) 3508.65,1157.81 R512.2@3515.01,1164.16
HOST_SPI_MOSI: R537.2 R538.2 U5.2 U7.V20 | length 2618.8
  Top Layer w6.2: v1(2198.55,304.53) 2198.55,323.62 2204.72,329.8 U5.2@2204.72,355.21 ; v2(3548.02,1129.42) U7.V20@3567.71,1109.73
  Signal Layer 1 w5.6: v1(2198.55,304.53) 2198.55,291.36 2202.38,287.53 2202.38,262.22 2271.99,192.61 2522.91,192.61 2605.34,110.18 2958.32,110.18 3026.04,177.9 3216.34,177.9 3361.82,323.38 3361.82,345.53 3508.77,492.48 3508.77,557.05 3528.76,577.05 3528.76,1110.15 v2(3548.02,1129.42)
  Bottom Layer w6.2: v1(2198.55,304.53) 2198.55,415.05 2188.64,424.95 2188.64,445.13 2200.88,457.37 2223.07,457.37 2243.77,478.07 2249.84,478.07 R537.2@2259.26,487.49 R538.2@2259.26,554.51
HOST_SPI_MOSI_S: C572.1 J2.5 R537.1 | length 191.7
  Top Layer w6.2: J2.5@2263.78,229.33 v1@2263.78,276.86
  Bottom Layer w6.2: R537.1@2259.26,407.49 2275.35,391.39 C572.1@2275.35,334.27 2277.65,331.97 2277.65,290.73 2263.78,276.86 v1(2263.78,276.66)
JTAGRSTZ: R24.2 U7.L20 | length 269.1
  Top Layer w6.2: R24.2@3160.88,1287.22 3172.76,1275.34 3172.76,1261.68 v2(3192.83,1241.6) ; U7.L20@3292.12,1109.73 v2(3311.8,1129.42)
  Bottom Layer w6.2: v2(3192.83,1241.6) 3210.04,1241.6 3263.3,1188.35 3281.91,1188.35 3311.8,1158.46 v2(3311.8,1129.42)
L1_CLK_N: J6.9 U7.AA11 U10.2 | length 525.8
  Top Layer w6.2: U7.AA11@3685.82,755.4 v2(3705.5,775.09) ; U10.2@3925.83,630.7 3938.62,630.7 3944.09,636.16 v1(3956.15,636.16) ; v1(4015.78,636.16) 4028.29,636.16 4033.75,630.7 J6.9@4056.1,630.7
  Signal Layer 1 w4: v2(3705.5,775.09) 3716.64,775.09 3721.19,779.63 3721.19,790.67 3729.29,798.77 3754.62,798.77 3756.2,800.35 3776.06,800.35 3802,774.41 3802,755.09 3930.74,626.35 3946.34,626.35 v1(3956.15,636.16) 3965.96,626.35 4005.97,626.35 v1(4015.78,636.16)
L1_CLK_P: J6.8 U7.AB11 U10.1 | length 512.5
  Top Layer w6.2: U7.AB11@3725.19,755.4 v2(3744.87,775.09) ; U10.1@3925.83,611.01 3938.62,611.01 3944.09,605.55 v1(3956.15,605.55) ; v1(4015.78,605.55) 4028.24,605.55 4033.7,611.01 J6.8@4056.1,611.01
  Signal Layer 1 w4: v2(3744.87,775.09) 3733.73,775.09 3729.19,779.63 3729.19,787.36 3732.6,790.77 3754.89,790.77 3756.31,789.35 3771.5,789.35 3791,769.86 3791,750.54 3926.18,615.35 3946.34,615.35 v1(3956.15,605.55) 3965.96,615.35 4005.97,615.35 v1(4015.78,605.55)
L1_DATA0_N: J6.3 U7.AA9 U11.2 | length 568.3
  Top Layer w6.2: U7.AA9@3685.82,676.66 v2(3705.5,696.35) ; U11.2@3925.83,512.59 3938.62,512.59 3944.09,518.05 v1(3956.15,518.05) ; v1(4015.78,518.05) 4028.29,518.05 4033.75,512.59 J6.3@4056.1,512.59
  Signal Layer 1 w4: v2(3705.5,696.35) 3716.64,696.35 3721.19,700.89 3721.19,711.93 3729.29,720.03 3754.62,720.03 3756.2,721.61 3783.53,721.61 3808.54,696.59 3814.98,690.15 3814.98,626.19 3932.93,508.24 3946.34,508.24 v1(3956.15,518.05) 3965.96,508.24 4005.97,508.24 v1(4015.78,518.05)
L1_DATA0_P: J6.2 U7.AB9 U11.1 | length 554.9
  Top Layer w6.2: U7.AB9@3725.19,676.66 v2(3744.87,696.35) ; U11.1@3925.83,492.9 3938.62,492.9 3944.09,487.44 v1(3956.15,487.44) ; v1(4015.78,487.44) 4028.24,487.44 4033.7,492.9 J6.2@4056.1,492.9
  Signal Layer 1 w4: v2(3744.87,696.35) 3733.73,696.35 3729.19,700.89 3729.19,708.62 3732.6,712.03 3754.89,712.03 3756.31,710.61 3778.97,710.61 3803.98,685.59 3803.98,621.63 3928.37,497.24 3946.34,497.24 v1(3956.15,487.44) 3965.96,497.24 4005.97,497.24 v1(4015.78,487.44)
L1_DATA1_N: J6.6 U7.AA10 U11.5 | length 563.3
  Top Layer w6.2: U7.AA10@3685.82,716.03 v2(3705.5,735.72) ; U11.5@3925.83,571.64 3938.62,571.64 3944.09,577.1 v1(3956.15,577.1) ; v1(4015.78,577.1) 4028.29,577.1 4033.75,571.64 J6.6@4056.1,571.64
  Signal Layer 2 w4: v2(3705.5,735.72) 3716.64,735.72 3721.19,740.26 3721.19,751.3 3729.29,759.4 3754.62,759.4 3756.2,760.98 3802.47,760.98 3915.83,647.62 3915.83,578.32 3926.95,567.19 3946.24,567.19 v1(3956.15,577.1)
  Signal Layer 1 w4: v1(3956.15,577.1) 3965.96,567.3 4005.97,567.3 v1(4015.78,577.1)
L1_DATA1_P: J6.5 U7.AB10 U11.4 | length 549.9
  Top Layer w6.2: U7.AB10@3725.19,716.03 v2(3744.87,735.72) ; U11.4@3925.83,551.96 3938.62,551.96 3944.09,546.49 v1(3956.15,546.49) ; v1(4015.78,546.49) 4028.24,546.49 4033.7,551.96 J6.5@4056.1,551.96
  Signal Layer 2 w4: v2(3744.87,735.72) 3733.73,735.72 3729.19,740.26 3729.19,747.99 3732.6,751.4 3754.89,751.4 3756.31,749.98 3797.91,749.98 3904.83,643.07 3904.83,573.76 3922.4,556.19 3946.45,556.19 v1(3956.15,546.49)
  Signal Layer 1 w4: v1(3956.15,546.49) 3965.96,556.3 4005.97,556.3 v1(4015.78,546.49)
L1_DATA2_N: J6.12 U7.AA12 U10.5 | length 521.7
  Top Layer w6.2: U7.AA12@3685.82,794.77 v2(3705.5,814.46) ; U10.5@3925.83,689.75 3938.62,689.75 3944.09,695.21 v1(3956.15,695.21) ; v1(4015.78,695.21) 4028.29,695.21 4033.75,689.75 J6.12@4056.1,689.75
  Signal Layer 1 w4: v2(3705.5,814.46) 3716.64,814.46 3721.19,819 3721.19,830.04 3729.29,838.14 3754.62,838.14 3756.2,839.72 3787.94,839.72 3836.21,791.45 3836.21,765.21 3916.01,685.41 3946.34,685.41 v1(3956.15,695.21) 3965.96,685.41 4005.97,685.41 v1(4015.78,695.21)
L1_DATA2_P: J6.11 U7.AB12 U10.4 | length 508.4
  Top Layer w6.2: U7.AB12@3725.19,794.77 v2(3744.87,814.46) ; U10.4@3925.83,670.07 3938.62,670.07 3944.09,664.6 v1(3956.15,664.6) ; v1(4015.78,664.6) 4028.24,664.6 4033.7,670.07 J6.11@4056.1,670.07
  Signal Layer 1 w4: v2(3744.87,814.46) 3733.73,814.46 3729.19,819 3729.19,826.73 3732.6,830.14 3754.89,830.14 3756.31,828.72 3783.38,828.72 3825.21,786.89 3825.21,760.65 3911.46,674.41 3946.34,674.41 v1(3956.15,664.6) 3965.96,674.41 4005.97,674.41 v1(4015.78,664.6)
L1_DATA3_N: J6.15 U7.AA13 U9.2 | length 507.4
  Top Layer w6.2: U7.AA13@3685.82,834.14 v2(3705.5,853.83) ; U9.2@3925.83,748.81 3938.62,748.81 3944.09,754.27 v1(3956.15,754.27) ; v1(4015.78,754.27) 4028.29,754.27 4033.75,748.81 J6.15@4056.1,748.81
  Signal Layer 1 w4: v2(3705.5,853.83) 3716.05,853.83 3719.41,857.19 3719.41,872.21 3734.65,887.45 3790.65,887.45 3933.63,744.46 3946.34,744.46 v1(3956.15,754.27) 3965.96,744.46 4005.97,744.46 v1(4015.78,754.27)
L1_DATA3_P: J6.14 U7.AB13 U9.1 | length 489.6
  Top Layer w6.2: U7.AB13@3725.19,834.14 v2(3744.87,853.83) ; U9.1@3925.83,729.12 3938.62,729.12 3944.09,723.66 v1(3956.15,723.66) ; v1(4015.78,723.66) 4028.24,723.66 4033.7,729.12 J6.14@4056.1,729.12
  Signal Layer 1 w4: v2(3744.87,853.83) 3733.96,853.83 3730.41,857.37 3730.41,867.65 3739.21,876.45 3786.09,876.45 3929.07,733.46 3946.34,733.46 v1(3956.15,723.66) 3965.96,733.46 4005.97,733.46 v1(4015.78,723.66)
LEDSEL_0: C560.1 J4.1 R523.2 R527.2 | length 469.7
  Top Layer w6.2: J4.1@2874.02,229.33 v1(2874.02,276.86)
  Signal Layer 2 w5.6: v1(2874.02,276.86) 2896.14,298.98 3055.02,298.98 3072.05,316.02 v2(3114.95,316.02)
  Bottom Layer w6.2: R527.2@2813.98,194.33 2813.98,239.33 C560.1@2818.98,244.33 2841.49,244.33 v1(2874.02,276.86) ; v2(3114.95,316.02) 3116.28,316.02 R523.2@3146.76,285.53
LEDSEL_0_S: R523.1 U7.F2 | length 89.6
  Top Layer w6.2: U7.F2@3095.27,401.07 v2(3114.95,381.38)
  Bottom Layer w6.2: v2(3114.95,381.38) 3114.95,369.58 3146.76,337.77 R523.1@3146.76,332.77
LEDSEL_1: C557.1 J4.2 R20.2 R525.2 | length 450.7
  Top Layer w6.2: R20.2@2813.98,294.33 2858.36,294.33 2863.76,299.73 2890.51,299.73 v1(2913.39,276.86) J4.2@2913.39,229.33
  Signal Layer 2 w5.6: v1(2913.39,276.86) 2935.04,255.2 3080.14,255.2 v2(3114.95,290.02)
  Bottom Layer w6.2: C557.1@2913.39,245.05 v1(2913.39,276.86) ; R525.2@3083.58,299.39 3092.96,290.02 v2(3114.95,290.02)
LEDSEL_1_S: R525.1 U7.G1 | length 61.1
  Top Layer w6.2: v2(3114.95,342.01) U7.G1@3134.64,361.7
  Bottom Layer w6.2: R525.1@3083.58,346.64 3088.2,342.01 v2(3114.95,342.01)
LEDSEL_2: C561.1 J4.3 R21.2 R526.2 | length 634.1
  Top Layer w6.2: R21.2@2813.98,359.33 2833.61,339.69 2889.92,339.69 v1(2952.76,276.86) J4.3@2952.76,229.33
  Bottom Layer w6.2: v1(2952.76,276.86) 2952.76,252.16 C561.1@2968.62,236.3 2995.93,208.98 3036.3,208.98 3078.19,250.86 3157.61,250.86 3171.26,264.51 3171.26,359.46 R526.2@3146.76,383.95
LEDSEL_2_S: R526.1 U7.G2 | length 64
  Top Layer w6.2: v2(3114.95,420.75) U7.G2@3134.64,401.07
  Bottom Layer w6.2: v2(3114.95,420.75) 3125.39,431.2 R526.1@3146.76,431.2
LEDSEL_3: C550.1 J4.4 R519.2 R528.2 | length 706.7
  Top Layer w6.2: v1(2830.41,403.02) 2852.04,381.38 2910.32,381.38 2918.1,373.61 2918.1,345.88 v1(2987.13,276.86) 2987.13,234.33 J4.4@2992.13,229.33
  Signal Layer 1 w5.6: v1(2987.13,276.86) 3015.47,305.2 3045.74,305.2 3102.35,361.81 3213.64,361.81 v2(3233.43,342.01)
  Bottom Layer w6.2: R528.2@2789.45,349.41 2830.41,390.38 v1(2830.41,403.02) ; C550.1@2984.25,311.2 2987.13,308.33 v1(2987.13,276.86) ; v2(3233.43,342.01) 3233.43,324.04 R519.2@3246.27,311.2
LEDSEL_3_S: R519.1 U7.H1 | length 60.9
  Top Layer w6.2: U7.H1@3174.01,361.7 v2(3193.69,342.01)
  Bottom Layer w6.2: v2(3193.69,342.01) 3193.69,316.54 R519.1@3199.02,311.2
LMR_VCC: C10.1 U2.5 | length 102.4
  Top Layer w10: U2.5@900.38,473.05 900.38,494.33 910.28,504.23
  Top Layer w15: 910.28,504.23 930.54,524.48 C10.1@930.54,562.93
NetC6_1: C6.1 L1.1 L2.2
NetC11_1: C11.1 R1.1 | length 66.1
  Top Layer w20: C11.1@969.19,1610.36 R1.1@969.19,1676.5
NetC42_1: C42.1 R18.1 Y1.3 | length 159.1
  Top Layer w6.2: Y1.3@2580.71,856.77 2580.71,861.07 2617.39,897.75 2617.39,904.55 C42.1@2636.04,923.21 2648.77,935.94 R18.1@2700.53,935.94
NetD1_1: D1.1 D2.1 | length 192
  Top Layer w20: D2.1@677.56,1574.8 D1.1@677.56,1766.81
NetFB502_2: FB502.2 J4.9 | length 257.5
  Top Layer w6.2: v1(3148.98,44.86) 3188.98,84.86 J4.9@3188.98,229.33
  Bottom Layer w6.2: v1(3148.98,44.86) 3149.29,44.86 FB502.2@3188.98,84.55
NetFB503_2: FB503.2 J4.8 | length 256.1
  Top Layer w6.2: v1(3102.48,44.86) 3149.61,91.99 J4.8@3149.61,229.33
  Bottom Layer w6.2: v1(3102.48,44.86) 3102.48,54.55 FB503.2@3132.48,84.55
NetFB504_2: FB504.2 J4.7 | length 254.9
  Top Layer w6.2: v1(3055.98,44.86) 3110.24,99.12 J4.7@3110.24,229.33
  Bottom Layer w6.2: v1(3055.98,44.86) 3055.98,64.55 FB504.2@3075.98,84.55
PLL_REFCLK_I: C46.1 R19.2 U7.D15 Y1.1 | length 542.8
  Top Layer w6.2: Y1.1@2647.63,770.15 C46.1@2706.1,770.15 R19.2@2774.86,770.15 v1(2826.36,770.15) ; U7.D15@3016.53,912.88 v2(3036.21,893.2)
  Signal Layer 2 w5.6: v1(2826.36,770.15) 2841.12,755.4 3006.24,755.4 3019.28,768.44 3019.28,876.26 v2(3036.21,893.2)
PLL_REFCLK_O: R18.2 R19.1 U7.D14 | length 385.9
  Top Layer w6.2: R18.2@2780.53,935.94 2774.86,930.28 R19.1@2774.86,850.15 v1(2826.36,850.15) ; v2(2996.84,893.2) U7.D14@3016.53,873.51
  Signal Layer 2 w5.6: v1(2826.36,850.15) 2842.38,834.14 2966.57,834.14 2977.19,844.77 2977.19,873.55 v2(2996.84,893.2)
PMIC_AD3_CLK: R522.2 U4.17 | length 1366.2
  Top Layer w6.2: U4.17@1917.32,558.05 1955.01,558.05 1967.69,570.73 v1(1990.68,570.73)
  Signal Layer 1 w5.6: v1(1990.68,570.73) 2139.18,570.73 2155.78,587.33 2202.05,587.33 2226.05,563.33 2303.42,563.33 2351.52,611.43 2504.78,611.43 2613.56,502.65 2696.68,502.65 2713.35,519.32 3046.36,519.32 3054.1,527.05 3107.2,527.05 3118.09,516.17 v2(3118.09,502.65)
  Bottom Layer w6.2: v2(3118.09,502.65) 3118.09,489.36 3128.8,478.65 R522.2@3150.64,478.65
PMIC_AD3_CLK_S: R522.1 U7.H2 | length 87.5
  Top Layer w6.2: U7.H2@3174.01,401.07 v2(3193.69,420.75)
  Bottom Layer w6.2: v2(3193.69,420.75) 3193.69,474.45 R522.1@3197.89,478.65
PMIC_AD3_MISO: R541.2 U4.4 U7.J2 | length 1647.7
  Top Layer w6.2: U4.4@1917.32,302.14 1978.44,302.14 2007.6,272.98 v1(2025.16,272.98) ; U7.J2@3213.38,401.07 v2(3233.06,381.38)
  Signal Layer 1 w5.6: v1(2025.16,272.98) 2034.49,263.65 2068.57,263.65 2082.92,278.01 2082.92,287.51 2132.05,336.63 2699.03,336.63 2782.69,252.98 3173.6,252.98 3252.8,332.18 3252.8,361.64 v2(3233.06,381.38)
  Bottom Layer w6.2: R541.2@1917.32,272.98 v1(2025.16,272.98)
PMIC_AD3_MOSI: R544.2 U4.5 U7.J1 | length 1501.4
  Top Layer w6.2: U4.5@1917.32,321.83 1989.26,321.83 2008.7,302.39 v1(2025.16,302.39) ; v2(3193.69,381.38) U7.J1@3213.38,361.7
  Signal Layer 1 w5.6: v1(2025.16,302.39) 2043.49,302.39 2097.99,356.89 2749.7,356.89 2765.32,341.27 2915.82,341.27 2936.39,361.83 3084.41,361.83 3095.22,372.65 3095.22,391.9 3104.37,401.05 3174.03,401.05 v2(3193.69,381.38)
  Bottom Layer w6.2: R544.2@1917.32,321.83 1936.76,302.39 v1(2025.16,302.39)
PMIC_AVDD: C20.1 C22.1 L5.2 U4.59 | length 206.2
  Top Layer w11.81: 1247.42,548.83 1263.3,548.83 1272.52,558.05 U4.59@1311.02,558.05
  Top Layer w20: L5.2@1110.31,544.72 C20.1@1172.64,544.72 1176.75,548.83 C22.1@1229.68,548.83 1247.42,548.83
PMIC_INTZ: R10.1 R524.1 U4.10 U7.G3 | length 1627.9
  Top Layer w6.2: U4.10@1917.32,420.25 2028.09,420.25 2052.53,444.69 R10.1@2052.53,465.53 2076.14,489.14 2105.43,489.14 v1(2133.96,517.68) ; v2(3114.95,460.12) U7.G3@3134.64,440.44
  Signal Layer 2 w5.6: v2(3038.22,616.16) 3059.58,594.8 3059.58,533.58 3044.6,518.6 3044.6,498.14 3059.47,483.28 3091.8,483.28 v2(3114.95,460.12)
  Signal Layer 1 w5.6: v1(2133.96,517.68) 2143.62,508.02 2277.45,508.02 2347.34,577.9 2389.21,577.9 2487.28,479.83 3095.25,479.83 v2(3114.95,460.12)
  Bottom Layer w6.2: v2(3038.22,616.16) 3038.22,627.3 R524.1@3065,654.08
PMIC_PARKZ: R530.2 U4.8 U7.E3 | length 1633.3
  Top Layer w6.2: U4.8@1917.32,380.88 1917.64,381.2 2001.81,381.2 2006.55,385.93 2040.83,385.93 v1(2052.73,374.03) ; U7.E3@3055.9,440.44 v2(3075.58,420.75)
  Signal Layer 1 w5.6: v1(2052.73,374.03) 2850.17,374.03 2876.77,400.63 3055.46,400.63 v2(3075.58,420.75)
  Bottom Layer w6.2: R530.2@2720.05,500.19 2847.12,500.19 2866.08,519.15 3005.61,519.15 3055.64,469.13 3055.64,440.7 v2(3075.58,420.75)
PMIC_SEQ_START: R9.2 R542.2 U4.7 U4.16 | length 658.9
  Top Layer w6.2: U4.7@1917.32,361.2 v1(2025.16,361.2) ; U4.16@1917.32,538.36 1960.6,538.36 1968.63,546.39 2036.15,546.39 R9.2@2056.41,566.65 v1(2056.41,598.71)
  Bottom Layer w6.2: v1(2025.16,361.2) 1976.69,361.2 R542.2@1917.32,420.57 1917.32,459.62 v1(2056.41,598.71)
PMIC_SEQ_START_S: R9.1 U7.K1 | length 1724.7
  Top Layer w6.2: R9.1@2103.65,566.65 v1(2103.65,598.71) ; U7.K1@3252.75,361.7 v2(3272.43,342.01)
  Signal Layer 2 w5.6: v1(2103.65,598.71) 2050.03,545.09 2010.56,545.09 1991.98,526.5 1991.98,439.45 2007.51,423.91 2034.83,423.91 2042.43,431.51 2065.47,431.51 2166.37,330.61 2321.43,330.61 2387.91,264.13 2464.87,264.13 2492.8,236.2 2727.09,236.2 2740.46,249.58 2834.85,249.58 2860.7,223.73 3154.15,223.73 v2(3272.43,342.01)
PMIC_SPI2_CLK: R518.2 R521.2 U4.34 | length 2280.9
  Top Layer w6.2: U4.34@1692.91,782.46 1692.91,815.75 1699.4,822.24 1704.46,822.24 v1(1712.6,830.38)
  Signal Layer 2 w5.6: v1(1712.6,830.38) 1769.35,773.62 1769.35,725.29 1802.43,692.22 1802.43,571.41 1814.59,559.24 1838.27,559.24 1992.39,405.12 1992.39,272.43 2015.36,249.46 2070.11,249.46 2204.47,115.1 2675.5,115.1 2729.5,169.11 2848.95,169.11 2882.7,135.35 2935.09,135.35 2968.32,168.58 v1(3240.16,168.58)
  Bottom Layer w6.2: v1(3240.16,168.58) 3262.32,146.41 3262.32,135.49 3290.44,107.36 R518.2@3294.01,107.36 R521.2@3379.47,107.36
PMIC_SPI2_CLK_S: C526.1 J5.1 R518.1 | length 170
  Top Layer w6.2: J5.1@3366.14,229.33 v1(3366.14,276.86)
  Bottom Layer w6.2: R518.1@3294.01,187.36 3299.3,187.36 3331.73,219.8 3331.73,228.7 C526.1@3350.07,247.05 3366.14,263.11 v1(3366.14,276.86)
PMIC_SPI2_MISO: C521.1 J5.3 R6.1 | length 2991.5
  Top Layer w6.2: R6.1@1713.02,919.27 1705.4,926.9 1705.4,963.16 1722.63,980.39 1898.32,980.39 1944.8,933.92 1944.8,886.54 2132.76,698.57 2132.76,553.13 v1(2107.96,528.34) ; J5.3@3444.88,229.33 3449.88,234.33 v1(3449.88,276.86)
  Signal Layer 1 w5.6: v1(2107.96,528.34) 2097.31,538.99 2015.4,538.99 1970.34,493.93 1970.34,163.39 2074.71,59.03 2990.33,59.03 3020.14,88.84 3261.86,88.84 v1(3449.88,276.86)
  Bottom Layer w6.2: v1(3449.88,276.86) 3449.88,250.24 C521.1@3453.07,247.05
PMIC_SPI2_MISO_S: R6.2 U4.32 | length 101.9
  Top Layer w6.2: R6.2@1713.02,872.03 1737.51,847.54 1737.51,823.47 1732.28,818.25 U4.32@1732.28,782.46
PMIC_SPI2_MOSI: R505.2 R509.2 U4.31 | length 2866.6
  Top Layer w6.2: v1(1746.97,734.16) 1751.97,739.16 U4.31@1751.97,782.46
  Signal Layer 2 w5.6: v1(1746.97,734.16) 1746.97,518.18 1758.97,506.18 1850.26,506.18 1967.16,389.28 1967.16,169.18 2089.65,46.69 2986.65,46.69 3025.54,85.58 3164.28,85.58 3203.17,46.69 3550.56,46.69 3744.39,240.52 v1(3744.39,292.02)
  Bottom Layer w6.2: R509.2@3667.84,330.08 R505.2@3744.39,330.08 v1(3744.39,292.02)
PMIC_SPI2_MOSI_S: C519.1 J5.5 R509.1 | length 160
  Top Layer w6.2: J5.5@3523.62,229.33 3528.62,234.33 v1(3528.62,276.86)
  Bottom Layer w6.2: v1(3528.62,276.86) 3528.62,290.72 3523.62,295.72 C519.1@3523.62,314.46 3539.24,330.08 R509.1@3587.84,330.08
PMIC_SPI_CLK: R8.2 U4.27 U7.E1 | length 1701.7
  Top Layer w6.2: U4.27@1830.71,782.46 1830.71,826.22 v1(1841.03,836.55) R8.2@1841.03,868.15 ; v2(3036.21,342.01) U7.E1@3055.9,361.7
  Signal Layer 2 w5.6: v1(1841.03,836.55) 1823.83,853.75 1792.83,853.75 1780.54,841.46 1780.54,810.93 1830.64,760.83 1975.02,760.83 2055.05,680.8 2142.8,680.8 2428.7,394.9 2699.02,394.9 2718.9,375.03 2787.31,375.03 2798.71,363.62 2841.27,363.62 2860.32,382.67 2930.67,382.67 2948.77,400.77 2977.45,400.77 v2(3036.21,342.01)
PMIC_SPI_MISO: U4.29 U7.F1 | length 1617.2
  Top Layer w6.2: v1(1791.34,734.16) U4.29@1791.34,782.46 ; v2(3075.58,381.38) U7.F1@3095.27,361.7
  Signal Layer 2 w5.6: v1(1791.34,734.16) 1830.97,734.16 1848.12,717.01 1911.34,717.01 1932.13,737.79 1974.44,737.79 2084.74,627.49 2109.8,627.49 2138.59,598.7 2138.59,570.73 2352.21,357.11 2679.86,357.11 2723.09,313.88 3044.19,313.88 3075.58,345.27 v2(3075.58,381.38)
